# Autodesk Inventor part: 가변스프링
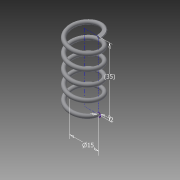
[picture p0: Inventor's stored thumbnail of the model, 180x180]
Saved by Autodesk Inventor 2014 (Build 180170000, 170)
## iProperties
Created: 2017-02
Part Number: 가변스프링
Material: 일반
Document SubType Name: Modeling
Designer: owner
Density: 1 g/cm^3
Appearance: 기본값
Author: owner
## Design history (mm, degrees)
sketch "스케치1"
  geometry: L1 (0, 0)-(7.5, 0); L2 (7.5, 0)-(7.5, 35); L3 (7.5, 35)-(0, 35); L4 (0, 35)-(0, 0); C1 r 1 at (7.5, 0)
  constraints: 8 end point, 2 parallel, 1 centre point, 1 coincident, 1 horizontal, 1 perpendicular
  dimensions: "d0" = 15 diameter of L2 L4; "d1" = 35 distance of L1.end L2.end (derived); "d2" = 2 diameter of C1
feature "코일1" pitch "d3" = 10; turns "d5" = 5; dims "d4" = 35 (= d1), "d6" = 0, angle "d7" = 90 deg, angle "d8" = 90 deg, "d9" = 0, "d10" = 0
sketch "스케치2"
  geometry: L1 (-6.5, 0)-(-8.5, 0) reference; 1 further point
  constraints: 1 horizontal alignment
extrude "돌출1" cut sketch "스케치2" stored distance "d11" = 10; taper "d12" = 0 deg
node "작업 평면1"
sketch "스케치3"
  geometry: L1 (-1, 0)-(1, 0) reference; 1 further point
  constraints: 1 horizontal alignment
extrude "돌출2" cut sketch "스케치3" stored distance "d13" = 10; taper "d14" = 0 deg
node "솔리드1"
node "절단 모서리 투영1"
node "절단 모서리 투영2"
